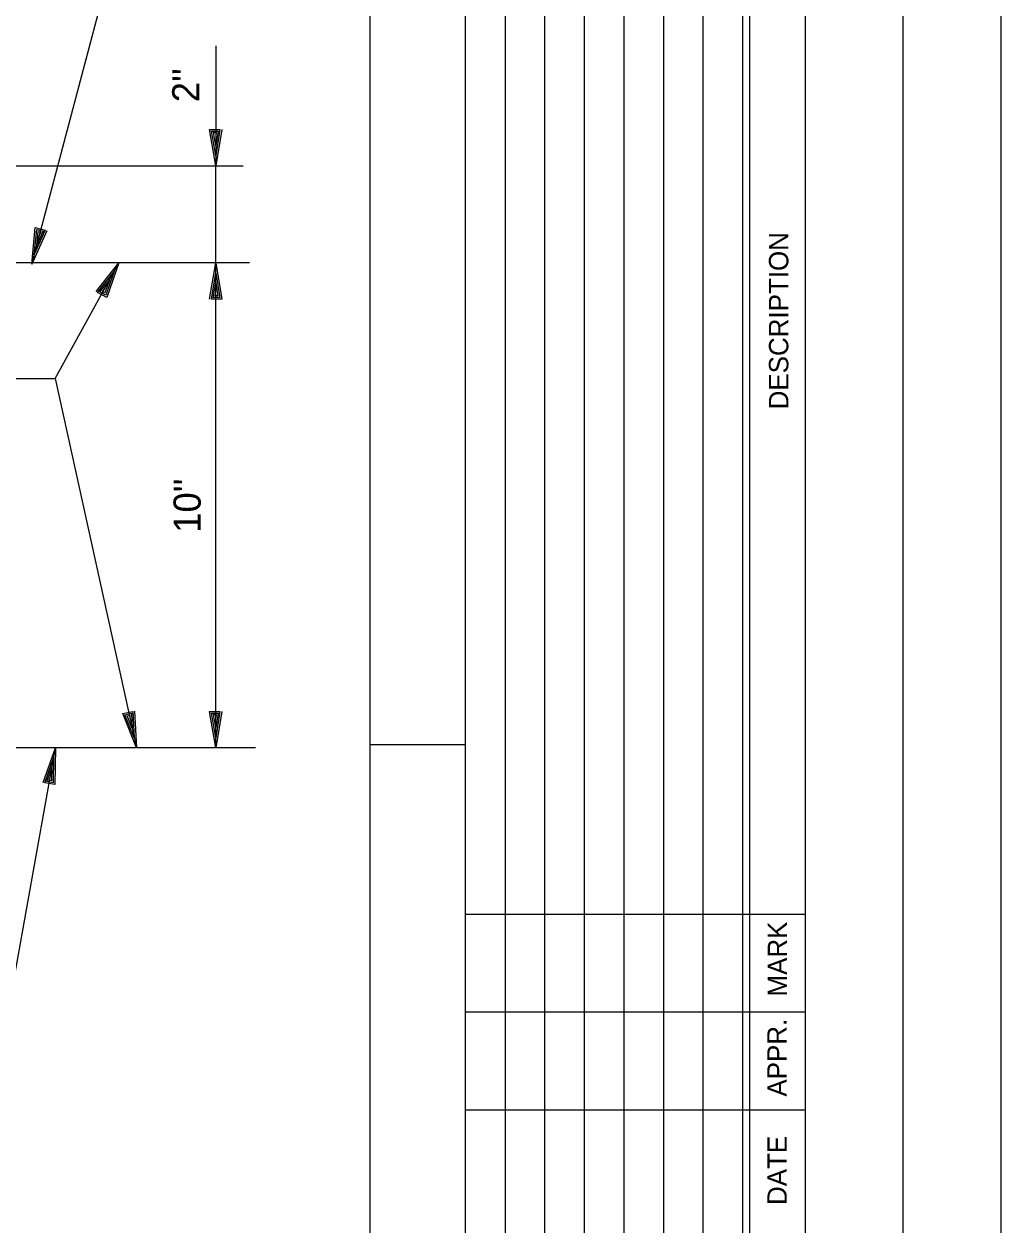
# Model space of a CAD drawing. Extents: x 22369.6 to 22384.3, y 22369.6 to 22381.8.
# Drawn here: x 22382.61 to 22384.288, y 22377.216 to 22379.279 of the extents above; entities that cross this region are included whole.
import ezdxf

# ---------------------------------------------------------------- set-up
doc = ezdxf.new("R2010")
doc.units = 0
for name, color, linetype in [('Level 1', 7, 'Continuous'), ('Level 10', 7, 'Continuous'), ('Level 4', 7, 'Continuous'), ('Level 7', 7, 'Continuous'), ('Level 9', 7, 'Continuous')]:
    doc.layers.add(name, color=color, linetype=linetype)

msp = doc.modelspace()

# ---------------------------------------------------------------- linework, layer by layer
at = {"layer": 'Level 1'}
for p, q in [((22382.6229, 22378.8668), (22382.9796, 22380.2088)), ((22383.4361, 22380.0813), (22383.4361, 22375.0813)), ((22383.5041, 22380.0813), (22383.5041, 22375.0813)), ((22383.5721, 22380.0813), (22383.5721, 22375.0813)), ((22383.6401, 22380.0813), (22383.6401, 22375.0813)), ((22383.7081, 22380.0813), (22383.7081, 22375.0813)), ((22383.7761, 22380.0813), (22383.7761, 22375.0813)), ((22383.8441, 22380.0813), (22383.8441, 22375.0813)), ((22383.8561, 22380.0813), (22383.8561, 22375.0813)), ((22382.939, 22379.242), (22382.939, 22379.0359)), ((22382.939, 22379.0532), (22382.939, 22379.0532)), ((22381.4883, 22379.0359), (22382.9862, 22379.0359)), ((22382.939, 22378.8692), (22382.939, 22379.0359)), ((22382.939, 22379.0359), (22382.939, 22379.0359)), ((22382.9969, 22378.8692), (22381.3556, 22378.8692)), ((22382.6229, 22378.8668), (22382.6229, 22378.8668)), ((22382.6274, 22378.8835), (22382.6274, 22378.8835)), ((22382.6631, 22378.6703), (22382.7727, 22378.8692)), ((22382.7727, 22378.8692), (22382.7727, 22378.8692)), ((22382.939, 22378.8692), (22382.939, 22378.8692)), ((22382.939, 22378.0359), (22382.939, 22378.8692)), ((22382.7644, 22378.854), (22382.7644, 22378.854)), ((22382.939, 22378.8519), (22382.939, 22378.8519)), ((22382.5267, 22378.6703), (22382.6631, 22378.6703)), ((22382.6631, 22378.6703), (22382.8027, 22378.0359)), ((22382.799, 22378.0528), (22382.799, 22378.0528)), ((22382.939, 22378.0532), (22382.939, 22378.0532)), ((22383.0076, 22378.0359), (22381.3556, 22378.0359)), ((22382.363, 22376.3572), (22382.6635, 22378.0359)), ((22382.6605, 22378.0188), (22382.6605, 22378.0188)), ((22382.6635, 22378.0359), (22382.6635, 22378.0359)), ((22382.8027, 22378.0359), (22382.8027, 22378.0359)), ((22382.939, 22378.0359), (22382.939, 22378.0359)), ((22383.9521, 22377.5813), (22383.3681, 22377.5813))]:
    msp.add_line(p, q, dxfattribs=at)
msp.add_lwpolyline([(22369.6213, 22380.9573), (22384.2881, 22380.9573), (22384.2881, 22369.6213), (22369.6213, 22369.6213)], close=True, dxfattribs=at)
for points in [[(22383.3681, 22375.1438), (22383.3681, 22380.0188)], [(22383.9521, 22375.1438), (22383.9521, 22380.0188)], [(22382.9493, 22379.0982), (22382.939, 22379.0359), (22382.9286, 22379.0982), (22382.9463, 22379.0982), (22382.939, 22379.0532), (22382.932, 22379.0955), (22382.9433, 22379.0955), (22382.939, 22379.0699), (22382.9353, 22379.0929), (22382.94, 22379.0929), (22382.939, 22379.0872)], [(22382.6489, 22378.9243), (22382.6229, 22378.8668), (22382.6289, 22378.9297), (22382.646, 22378.9251), (22382.6274, 22378.8835), (22382.6315, 22378.9262), (22382.6424, 22378.9233), (22382.6316, 22378.8996), (22382.634, 22378.9228), (22382.6385, 22378.9216), (22382.6361, 22378.9164)], [(22382.7336, 22378.8196), (22382.7727, 22378.8692), (22382.7517, 22378.8096), (22382.7362, 22378.8181), (22382.7644, 22378.854), (22382.7501, 22378.8136), (22382.7401, 22378.819), (22382.7563, 22378.8394), (22382.7484, 22378.8175), (22382.7443, 22378.8197), (22382.7479, 22378.8242)], [(22382.9286, 22378.8069), (22382.939, 22378.8692), (22382.9493, 22378.8069), (22382.9316, 22378.8069), (22382.939, 22378.8519), (22382.946, 22378.8095), (22382.9346, 22378.8095), (22382.939, 22378.8352), (22382.9426, 22378.8122), (22382.938, 22378.8122), (22382.939, 22378.8179)], [(22382.7994, 22378.0989), (22382.8027, 22378.0359), (22382.7792, 22378.0945), (22382.7965, 22378.0983), (22382.799, 22378.0528), (22382.783, 22378.0926), (22382.7941, 22378.0951), (22382.7954, 22378.0691), (22382.7869, 22378.0907), (22382.7914, 22378.0917), (22382.7917, 22378.086)], [(22382.9493, 22378.0982), (22382.939, 22378.0359), (22382.9286, 22378.0982), (22382.9463, 22378.0982), (22382.939, 22378.0532), (22382.932, 22378.0955), (22382.9433, 22378.0955), (22382.939, 22378.0699), (22382.9353, 22378.0929), (22382.94, 22378.0929), (22382.939, 22378.0872)], [(22382.6424, 22377.9763), (22382.6635, 22378.0359), (22382.6627, 22377.9727), (22382.6453, 22377.9758), (22382.6605, 22378.0188), (22382.6599, 22377.9759), (22382.6487, 22377.9779), (22382.6575, 22378.0024), (22382.6571, 22377.9791), (22382.6525, 22377.9799), (22382.6545, 22377.9853)]]:
    msp.add_lwpolyline(points, dxfattribs=at)
at = {"layer": 'Level 10'}
msp.add_line((22383.2041, 22378.0413), (22383.3681, 22378.0413), dxfattribs=at)
at = {"layer": 'Level 7'}
msp.add_line((22383.9521, 22377.4133), (22383.3681, 22377.4133), dxfattribs=at)
msp.add_lwpolyline([(22383.9521, 22377.7493), (22383.3681, 22377.7493)], dxfattribs=at)
at = {"layer": 'Level 9'}
msp.add_line((22384.1201, 22369.7893), (22384.1201, 22380.7893), dxfattribs=at)
msp.add_lwpolyline([(22383.2041, 22369.7893), (22383.2041, 22380.7893)], dxfattribs=at)

# ---------------------------------------------------------------- texts
at = {"layer": 'Level 1'}
for s, height, p in [('DESCRIPTION', 0.033333, (22383.9228, 22378.6173)), ('MARK', 0.03333, (22383.9207, 22377.6085)), ('APPR.', 0.03333, (22383.9201, 22377.4365)), ('DATE', 0.03333, (22383.9201, 22377.2503))]:
    msp.add_text(s, height=height, rotation=90, dxfattribs=at).set_placement(p)
at = {"layer": 'Level 4'}
for s, p in [("2''", (22382.9109, 22379.1451)), ("10''", (22382.9132, 22378.4054))]:
    msp.add_text(s, height=0.04667, rotation=90, dxfattribs=at).set_placement(p)

doc.saveas('drawing.dxf')
